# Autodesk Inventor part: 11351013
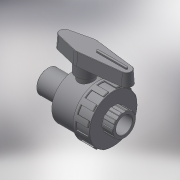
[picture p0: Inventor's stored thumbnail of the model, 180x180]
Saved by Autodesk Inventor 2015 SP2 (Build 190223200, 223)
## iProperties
Created: 2017-11
Part Number: 11351013
Material: Generic
Description: PLASSON 1/NUT VALVE FEMALE THREADED 1 1/4" PVC
Document SubType Name: Modeling
Designer: KIM
Density: 1 g/cm^3
Appearance: Default
Author: KIM
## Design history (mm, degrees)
derived "113510.ipt"
feature "Solid1::113510.ipt"
tag "TaggingFeature1"
body "Solid1"
other parameters: "d0" = 116, "d4" = 31.1616, "d8" = 72, "d13" = 1.16856, "d25" = 0.77904, "d26" = 1.16856, "d29" = 19.5, "d30" = 0, "d35" = 1.16856, "d45" = 360 deg, "d47" = 0.77904, "d50" = 44, "d51" = 24, "d53" = 0, "d55" = 7.7904, "d56" = 3.8952, "d57" = 18.2, "d58" = 0, "d59" = 1.16856, "d63" = 32, "d64" = 74, "d66" = 96, "d68" = 16, "d69" = 28.8, "d70" = 18.5, "d71" = 3 deg, "d73" = 1.6, "d74" = 38.4, "d75" = 2.22, "d76" = 0, "d77" = 0.77904, "d78" = 38.952, "d79" = 26, "d81" = 26, "d82" = 76.8, "d83" = 18.2, "d84" = 54.5328, "d85" = 38.952, "d86" = 54.5328, "d87" = 120 deg, "d88" = 26, "d90" = 360 deg, "d92" = 12, "d95" = 6, "G_" = 38.952, "l_" = 26, "H_" = 116, "F_" = 74, "J_" = 96, "d67" = 32, "d72" = 8
